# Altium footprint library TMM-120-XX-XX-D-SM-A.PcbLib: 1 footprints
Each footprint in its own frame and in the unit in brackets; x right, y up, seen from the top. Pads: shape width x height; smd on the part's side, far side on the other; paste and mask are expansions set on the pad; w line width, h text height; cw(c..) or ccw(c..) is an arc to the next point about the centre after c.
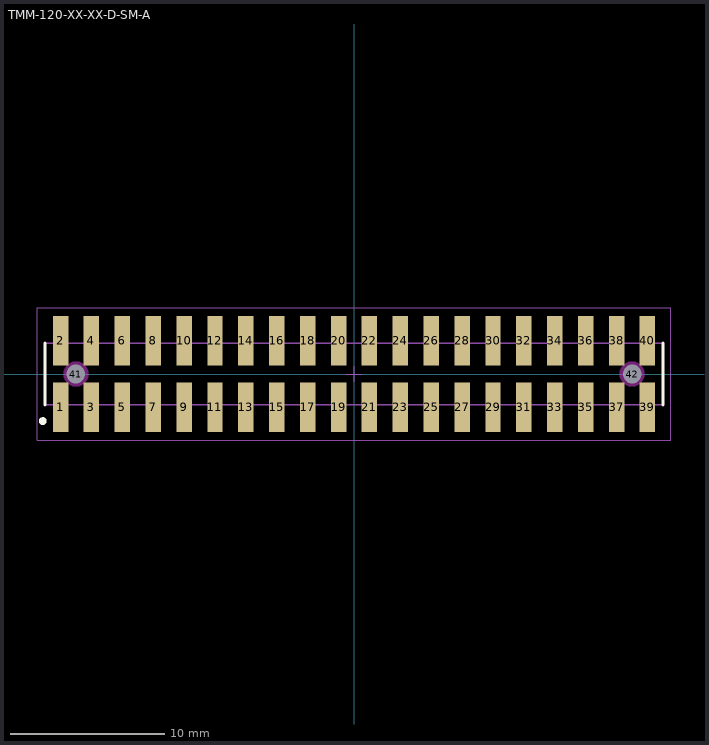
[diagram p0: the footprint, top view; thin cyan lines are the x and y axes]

## TMM-120-XX-XX-D-SM-A [mm] "2.00mm pitch, 40 pin, terminal strip; double row, w/alignment pins, SMT"
height 2.77
pads (42):
  rect 1x3.2 smd mask+0: 1(-19,-2.15) 2(-19,2.15) 3(-17,-2.15) 4(-17,2.15) 5(-15,-2.15) 6(-15,2.15) 7(-13,-2.15) 8(-13,2.15) 9(-11,-2.15) 10(-11,2.15) 11(-9,-2.15) 12(-9,2.15) 13(-7,-2.15) 14(-7,2.15) 15(-5,-2.15) 16(-5,2.15) 17(-3,-2.15) 18(-3,2.15) 19(-1,-2.15) 20(-1,2.15) 21(1,-2.15) 22(1,2.15) 23(3,-2.15) 24(3,2.15) 25(5,-2.15) 26(5,2.15) 27(7,-2.15) 28(7,2.15) 29(9,-2.15) 30(9,2.15) 31(11,-2.15) 32(11,2.15) 33(13,-2.15) 34(13,2.15) 35(15,-2.15) 36(15,2.15) 37(17,-2.15) 38(17,2.15) 39(19,-2.15) 40(19,2.15)
  round 1 hole 1.2 unplated mask+0: 41(-18,0) 42(18,0)
Top Overlay:
  circle w0.25: c-20.15,-3.05 r0.125
  lines w0.2: -20,-2 -20,2 ; 20,-2 20,2
Keep-Out Layer:
  pour cut-out: -17.193,0 -17.221,0.209 -17.301,0.403 -17.429,0.571 -17.597,0.699 -17.791,0.779 -18,0.807 -18.209,0.779 -18.403,0.699 -18.571,0.571 -18.699,0.403 -18.779,0.209 -18.807,0 -18.779,-0.209 -18.699,-0.403 -18.571,-0.571 -18.403,-0.699 -18.209,-0.779 -18,-0.807 -17.791,-0.779 -17.597,-0.699 -17.429,-0.571 -17.301,-0.403 -17.221,-0.209
  pour cut-out: 18.807,0 18.779,0.209 18.699,0.403 18.571,0.571 18.403,0.699 18.209,0.779 18,0.807 17.791,0.779 17.597,0.699 17.429,0.571 17.301,0.403 17.221,0.209 17.193,0 17.221,-0.209 17.301,-0.403 17.429,-0.571 17.597,-0.699 17.791,-0.779 18,-0.807 18.209,-0.779 18.403,-0.699 18.571,-0.571 18.699,-0.403 18.779,-0.209
Mechanical 12:
  lines w0.001: -20,-2 20,-2 20,2 -20,2 -20,-2
Mechanical 13:
  lines w0.1: -20,-2 20,-2 20,2 -20,2 -20,-2
  text ".Designator" at 0,-0.127 h1.52
Mechanical 15:
  lines w0.05: -0.5,0 0.5,0 ; 0,-0.5 0,0.5 ; -20.5,-4.3 20.5,-4.3 20.5,4.3 -20.5,4.3 -20.5,-4.3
